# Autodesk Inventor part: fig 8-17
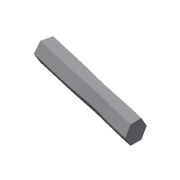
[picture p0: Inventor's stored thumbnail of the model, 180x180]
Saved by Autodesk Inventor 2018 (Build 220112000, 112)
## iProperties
Created: 2004-05
Part Number: fig 8-17
Document SubType Name: Modeling
Designer: CADCIM Technologies
Manufacturer: Standard
Standards Organization: Custom
Density: 1 g/cm^3
Material: Generic
Appearance: Default
Author: CADCIM Technologies
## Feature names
1. Sweep7
## Parameters: d6 = 0, d7 = 0
